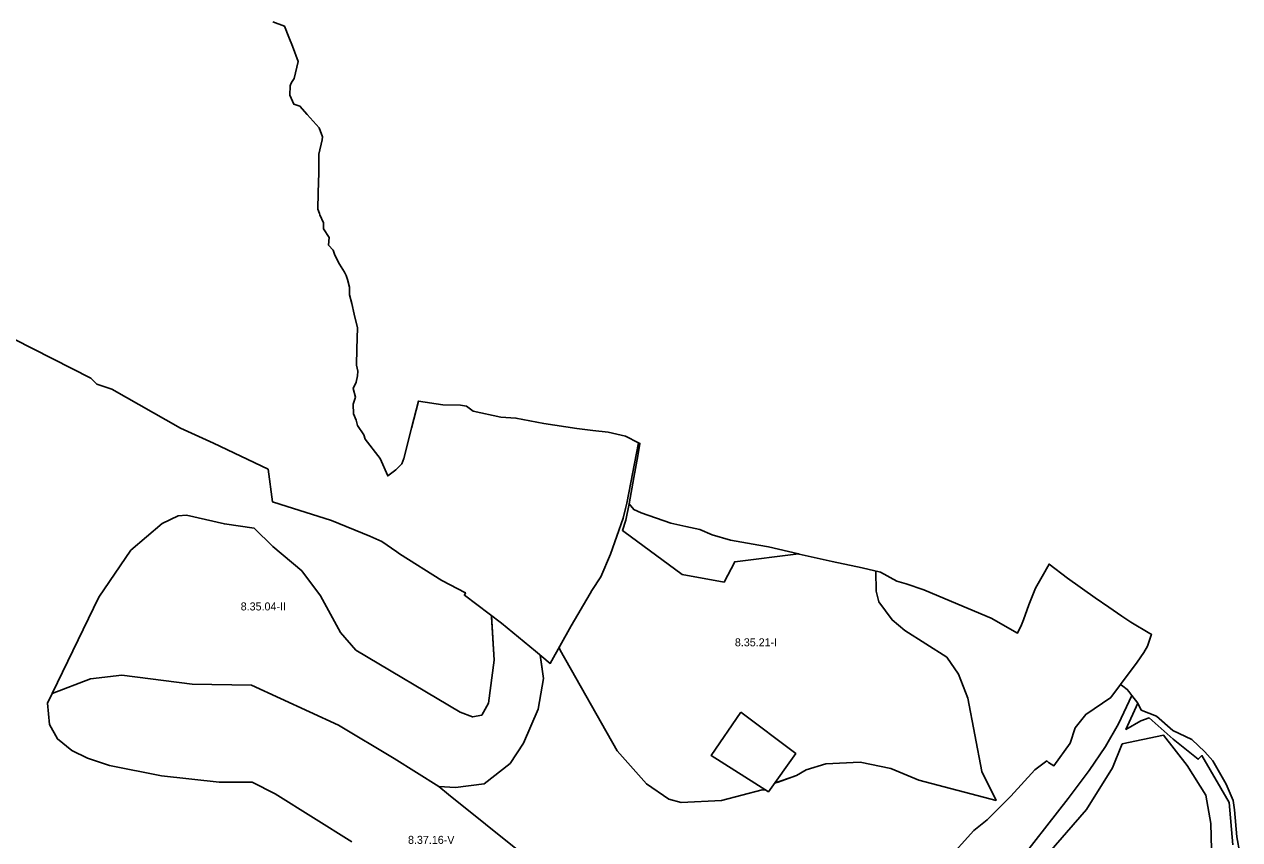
# Model space of a CAD drawing. Extents: x -547623 to -533936, y -1096714 to -1086523.
# Drawn here: x -542784 to -541266, y -1091207 to -1090189 of the extents above; entities that cross this region are included whole.
import ezdxf

# ---------------------------------------------------------------- set-up
doc = ezdxf.new("R2010")
doc.units = 0
for name, color, linetype in [('Vrstva 27', 7, 'Continuous'), ('Vrstva 28', 7, 'Continuous'), ('Vrstva 29', 7, 'Continuous')]:
    doc.layers.add(name, color=color, linetype=linetype)

msp = doc.modelspace()

# ---------------------------------------------------------------- linework, layer by layer
at = {"layer": 'Vrstva 28'}
for p, q in [((-542612, -1090812.5), (-542592, -1090803)), ((-542592, -1090803), (-542612, -1090812.5)), ((-542592, -1090803), (-542581.5, -1090802)), ((-542581.5, -1090802), (-542592, -1090803)), ((-542581.5, -1090802), (-542534, -1090813)), ((-542534, -1090813), (-542581.5, -1090802)), ((-542651, -1090846), (-542612, -1090812.5)), ((-542612, -1090812.5), (-542651, -1090846)), ((-542534, -1090813), (-542497, -1090818.5)), ((-542497, -1090818.5), (-542534, -1090813)), ((-542497, -1090818.5), (-542473.5, -1090841.5)), ((-542473.5, -1090841.5), (-542497, -1090818.5)), ((-542691, -1090904.5), (-542651, -1090846)), ((-542651, -1090846), (-542691, -1090904.5)), ((-542473.5, -1090841.5), (-542437.5, -1090871.5)), ((-542437.5, -1090871.5), (-542473.5, -1090841.5)), ((-541780.9, -1090858.6), (-541780.9, -1090858.6)), ((-542437.5, -1090871.5), (-542414, -1090903)), ((-542414, -1090903), (-542437.5, -1090871.5)), ((-541720.5, -1090871.9), (-541720.5, -1090871.9)), ((-542749, -1091025), (-542691, -1090904.5)), ((-542691, -1090904.5), (-542749, -1091025)), ((-542414, -1090903), (-542389, -1090948.5)), ((-542389, -1090948.5), (-542414, -1090903)), ((-542200.6, -1090927.6), (-542197, -1090983)), ((-542197, -1090983), (-542200.5, -1090929)), ((-542389, -1090948.5), (-542370, -1090970.5)), ((-542370, -1090970.5), (-542389, -1090948.5)), ((-542370, -1090970.5), (-542239.5, -1091048)), ((-542239.5, -1091048), (-542370, -1090970.5)), ((-542204, -1091037), (-542197, -1090983)), ((-542197, -1090983), (-542204, -1091037)), ((-542662, -1091002), (-542701.5, -1091006.5)), ((-542701.5, -1091006.5), (-542662, -1091002)), ((-542574.5, -1091013), (-542662, -1091002)), ((-542662, -1091002), (-542574.5, -1091013)), ((-542701.5, -1091006.5), (-542749, -1091025)), ((-542749, -1091025), (-542701.5, -1091006.5)), ((-542500, -1091014.5), (-542574.5, -1091013)), ((-542574.5, -1091013), (-542500, -1091014.5)), ((-542391.5, -1091064.5), (-542500, -1091014.5)), ((-542500, -1091014.5), (-542391.5, -1091064.5)), ((-542135.5, -1091006), (-542142, -1091044.5)), ((-542749, -1091025), (-542755, -1091037)), ((-542755, -1091037), (-542749, -1091025)), ((-542755, -1091037), (-542752.5, -1091063.5)), ((-542752.5, -1091063.5), (-542755, -1091037)), ((-542239.5, -1091048), (-542224, -1091054)), ((-542224, -1091054), (-542239.5, -1091048)), ((-542212.5, -1091052), (-542204, -1091037)), ((-542204, -1091037), (-542212.5, -1091052)), ((-542142, -1091044.5), (-542160.5, -1091087)), ((-542224, -1091054), (-542212.5, -1091052)), ((-542212.5, -1091052), (-542224, -1091054)), ((-542752.5, -1091063.5), (-542742.5, -1091081.5)), ((-542742.5, -1091081.5), (-542752.5, -1091063.5)), ((-542322, -1091106), (-542391.5, -1091064.5)), ((-542391.5, -1091064.5), (-542322, -1091106)), ((-542742.5, -1091081.5), (-542724.5, -1091096)), ((-542724.5, -1091096), (-542742.5, -1091081.5)), ((-542160.5, -1091087), (-542177, -1091112)), ((-542724.5, -1091096), (-542705, -1091105.5)), ((-542705, -1091105.5), (-542724.5, -1091096)), ((-542705, -1091105.5), (-542677.5, -1091114.5)), ((-542677.5, -1091114.5), (-542705, -1091105.5)), ((-542266, -1091141), (-542322, -1091106)), ((-542322, -1091106), (-542266, -1091141)), ((-542677.5, -1091114.5), (-542612.5, -1091127.5)), ((-542612.5, -1091127.5), (-542677.5, -1091114.5)), ((-542177, -1091112), (-542209.5, -1091137.5)), ((-542612.5, -1091127.5), (-542540.5, -1091135.5)), ((-542540.5, -1091135.5), (-542612.5, -1091127.5)), ((-542540.5, -1091135.5), (-542499.5, -1091135.5)), ((-542499.5, -1091135.5), (-542540.5, -1091135.5)), ((-542499.5, -1091135.5), (-542470.5, -1091150)), ((-542470.5, -1091150), (-542499.5, -1091135.5)), ((-542209.5, -1091137.5), (-542245.5, -1091142)), ((-542470.5, -1091150), (-542375, -1091210)), ((-542375, -1091210), (-542470.5, -1091150)), ((-542245.5, -1091142), (-542266, -1091141)), ((-542266, -1091141), (-542254, -1091151)), ((-542254, -1091151), (-542161.5, -1091225))]:
    msp.add_line(p, q, dxfattribs=at)
for points in [[(-542796.8, -1090582.4), (-542700.9, -1090631.2), (-542693.2, -1090638.7), (-542674.6, -1090645), (-542588.8, -1090693.4), (-542547.8, -1090712.1), (-542479.5, -1090744.8), (-542473.9, -1090785.7), (-542464.9, -1090788.5), (-542400.3, -1090808.8), (-542352.2, -1090828.5), (-542337.4, -1090835), (-542318.8, -1090848), (-542315.2, -1090850.3), (-542262.4, -1090883.7), (-542232.9, -1090899.1), (-542234.2, -1090902.1), (-542187.9, -1090937.2), (-542145.5, -1090972), (-542127.1, -1090987.2), (-542100.8, -1090940.4), (-542077.2, -1090899.8), (-542075.2, -1090896.3), (-542063.8, -1090879.2), (-542051.9, -1090850.9), (-542035.8, -1090806), (-542033, -1090793.8), (-542031.5, -1090787), (-542017, -1090711.7), (-542033.2, -1090703.4), (-542054.6, -1090698.6), (-542073.8, -1090696.3), (-542093.9, -1090693.9), (-542135, -1090687.7), (-542170, -1090680.9), (-542188.7, -1090679.9), (-542223.5, -1090672.4), (-542231.8, -1090666.1), (-542239, -1090664.9), (-542261.2, -1090664.6), (-542291.7, -1090659.8), (-542300.3, -1090693.7), (-542310.1, -1090731.5), (-542312.5, -1090738.1), (-542320, -1090745.4), (-542330, -1090753.1), (-542339.5, -1090731.6), (-542358.4, -1090707.5), (-542359.9, -1090702.1), (-542368, -1090690.2), (-542369.6, -1090683.6), (-542372.8, -1090675.5), (-542373.2, -1090663.6), (-542370.5, -1090655), (-542373.2, -1090644.1), (-542369.3, -1090636), (-542368, -1090628.1), (-542367.4, -1090622.4), (-542369.1, -1090614.8), (-542368.5, -1090594.5), (-542367.8, -1090568.4), (-542371.8, -1090551.4), (-542375, -1090538.1), (-542377.6, -1090527), (-542377.6, -1090517.7), (-542380.4, -1090507.8), (-542381.9, -1090503), (-542384.1, -1090499), (-542390.1, -1090488.8), (-542396, -1090477.8), (-542398.2, -1090471.5), (-542403.9, -1090465.1), (-542403.2, -1090455.5), (-542410.1, -1090444.7), (-542410.1, -1090437.1), (-542414.7, -1090427.3), (-542415.4, -1090425.6), (-542417.2, -1090420.1), (-542416.9, -1090399.8), (-542416.3, -1090374.6), (-542416.1, -1090351.7), (-542411.8, -1090333.5), (-542411.6, -1090329.8), (-542415.8, -1090318.7), (-542430.8, -1090301.9), (-542439.8, -1090291.6), (-542447.3, -1090289.2), (-542452.2, -1090277.8), (-542452, -1090266.3), (-542451.1, -1090263.9), (-542449.4, -1090261), (-542446.9, -1090257), (-542442.1, -1090235.8), (-542449.2, -1090216.6), (-542453.4, -1090205.5), (-542458.8, -1090191.6), (-542473.6, -1090186.5)], [(-541265.8, -1091224.5), (-541269.6, -1091203.8), (-541272.5, -1091169.9), (-541273.9, -1091158.3), (-541282.7, -1091138), (-541299.3, -1091108.7), (-541309.3, -1091097.6), (-541325.8, -1091082.1), (-541349.2, -1091070.9), (-541369.6, -1091053.2), (-541388.8, -1091045.5), (-541393.2, -1091036.7), (-541400.5, -1091027.1), (-541404.2, -1091022.4), (-541406.2, -1091019.8), (-541411.8, -1091015.7), (-541414.9, -1091013.4), (-541393.8, -1090985.6), (-541385.4, -1090973.5), (-541380.8, -1090965.8), (-541376.2, -1090950.9), (-541378.2, -1090949.7), (-541401.9, -1090935.6), (-541413.2, -1090928.4), (-541429.2, -1090917), (-541446.3, -1090905.3), (-541480.9, -1090880.7), (-541504, -1090863.2), (-541512.7, -1090878.9), (-541521.1, -1090893.2), (-541529.2, -1090914.2), (-541535.8, -1090932.7), (-541538.2, -1090939.1), (-541543.5, -1090949.6), (-541576.4, -1090930.9), (-541633.8, -1090906.6), (-541660.2, -1090895.4), (-541682.5, -1090888.1), (-541694.1, -1090884.6), (-541714.3, -1090873.4), (-541737.4, -1090868), (-541774.7, -1090860), (-541816, -1090850.8), (-541817, -1090850.6), (-541854.4, -1090841.9), (-541866.3, -1090839.7), (-541901.8, -1090833.5), (-541924.7, -1090826.6), (-541940.3, -1090819.9), (-541957.5, -1090816.4), (-541976.2, -1090812.2), (-542013.6, -1090799.4), (-542022.7, -1090794.9), (-542028.3, -1090788.2), (-542022.6, -1090755.3), (-542017.6, -1090728.1), (-542015, -1090712.7), (-542017, -1090711.7), (-542033.2, -1090703.4), (-542054.6, -1090698.6), (-542073.8, -1090696.3), (-542093.9, -1090693.9), (-542135, -1090687.7), (-542170, -1090680.9), (-542188.7, -1090679.9), (-542223.5, -1090672.4), (-542231.8, -1090666.1), (-542239, -1090664.9), (-542261.2, -1090664.6), (-542291.7, -1090659.8), (-542300.3, -1090693.7), (-542310.1, -1090731.5), (-542312.5, -1090738.1), (-542320, -1090745.4), (-542330, -1090753.1), (-542339.5, -1090731.6), (-542358.4, -1090707.5), (-542359.9, -1090702.1), (-542368, -1090690.2), (-542369.6, -1090683.6), (-542372.8, -1090675.5), (-542373.2, -1090663.6), (-542370.5, -1090655), (-542373.2, -1090644.1), (-542369.3, -1090636), (-542368, -1090628.1), (-542367.4, -1090622.4), (-542369.1, -1090614.8), (-542368.5, -1090594.5), (-542367.8, -1090568.4), (-542371.8, -1090551.4), (-542375, -1090538.1), (-542377.6, -1090527), (-542377.6, -1090517.7), (-542380.4, -1090507.8), (-542381.9, -1090503), (-542384.1, -1090499), (-542390.1, -1090488.8), (-542396, -1090477.8), (-542398.2, -1090471.5), (-542403.9, -1090465.1), (-542403.2, -1090455.5), (-542410.1, -1090444.7), (-542410.1, -1090437.1), (-542414.7, -1090427.3), (-542415.4, -1090425.6), (-542417.2, -1090420.1), (-542416.9, -1090399.8), (-542416.3, -1090374.6), (-542416.1, -1090351.7), (-542411.8, -1090333.5), (-542411.6, -1090329.8), (-542415.8, -1090318.7), (-542430.8, -1090301.9), (-542439.8, -1090291.6), (-542447.3, -1090289.2), (-542452.2, -1090277.8), (-542452, -1090266.3), (-542451.1, -1090263.9), (-542449.4, -1090261), (-542446.9, -1090257), (-542442.1, -1090235.8), (-542449.2, -1090216.6), (-542453.4, -1090205.5), (-542458.8, -1090191.6), (-542473.6, -1090186.5)], [(-541909.8, -1090886), (-541896.6, -1090860.3), (-541817, -1090850.6), (-541854.4, -1090841.9), (-541866.3, -1090839.7), (-541901.8, -1090833.5), (-541924.7, -1090826.6), (-541940.3, -1090819.9), (-541957.5, -1090816.4), (-541976.2, -1090812.2), (-542013.6, -1090799.4), (-542022.7, -1090794.9), (-542028.3, -1090788.2), (-542032.7, -1090808.6), (-542036.9, -1090821.2), (-542035.1, -1090822.6), (-541962.2, -1090876.3), (-541909.8, -1090886)], [(-542239.5, -1091048), (-542370, -1090970.5), (-542389, -1090948.5), (-542414, -1090903), (-542437.5, -1090871.5), (-542473.5, -1090841.5), (-542497, -1090818.5), (-542534, -1090813), (-542581.5, -1090802), (-542592, -1090803), (-542612, -1090812.5), (-542651, -1090846), (-542691, -1090904.5), (-542749, -1091025), (-542701.5, -1091006.5), (-542662, -1091002), (-542574.5, -1091013), (-542500, -1091014.5), (-542391.5, -1091064.5), (-542322, -1091106), (-542266, -1091141), (-542245.5, -1091142), (-542209.5, -1091137.5), (-542177, -1091112), (-542160.5, -1091087), (-542142, -1091044.5), (-542135.5, -1091006), (-542139.7, -1090976.9)], [(-541780.9, -1090858.6), (-541780.9, -1090858.6)], [(-541720.5, -1090871.9), (-541720, -1090897), (-541716.5, -1090910.5), (-541700, -1090933), (-541684, -1090946), (-541631.5, -1090979.5), (-541617, -1091000.5), (-541605.5, -1091030.5), (-541588, -1091122), (-541570.1, -1091158.2), (-541666.5, -1091133), (-541701.5, -1091118.5), (-541740, -1091110.5), (-541783, -1091112.5), (-541807.5, -1091120), (-541819.5, -1091127), (-541846.9, -1091136.9)], [(-541843.7, -1091135.7), (-541819.5, -1091127), (-541807.5, -1091120), (-541783, -1091112.5), (-541740, -1091110.5), (-541701.5, -1091118.5), (-541666.5, -1091133), (-541570.1, -1091158.2), (-541588, -1091122), (-541605.5, -1091030.5), (-541617, -1091000.5), (-541631.5, -1090979.5), (-541684, -1090946), (-541700, -1090933), (-541716.5, -1090910.5), (-541720, -1090897), (-541720.5, -1090871.9)], [(-542200.5, -1090929), (-542197, -1090983), (-542204, -1091037), (-542212.5, -1091052), (-542224, -1091054), (-542239.5, -1091048)], [(-542116.1, -1090967.5), (-542114.5, -1090970.5), (-542043.5, -1091096.5), (-542007, -1091137.5), (-541979, -1091156.5), (-541963.5, -1091161), (-541913, -1091158.5), (-541862.5, -1091145), (-541858, -1091145.3)], [(-542176.8, -1091480.2), (-542147, -1091427), (-542133.5, -1091384.5), (-542112, -1091362), (-542125, -1091305), (-542132, -1091278.5), (-542142.5, -1091252), (-542161.5, -1091225), (-542254, -1091151), (-542266, -1091141), (-542245.5, -1091142), (-542209.5, -1091137.5), (-542177, -1091112), (-542160.5, -1091087), (-542142, -1091044.5), (-542135.5, -1091006), (-542138.9, -1090982.2)], [(-542161.5, -1091225), (-542254, -1091151), (-542266, -1091141), (-542322, -1091106), (-542391.5, -1091064.5), (-542500, -1091014.5), (-542574.5, -1091013), (-542662, -1091002), (-542701.5, -1091006.5), (-542749, -1091025), (-542755, -1091037), (-542752.5, -1091063.5), (-542742.5, -1091081.5), (-542724.5, -1091096), (-542705, -1091105.5), (-542677.5, -1091114.5), (-542612.5, -1091127.5), (-542540.5, -1091135.5), (-542499.5, -1091135.5), (-542470.5, -1091150), (-542375, -1091210)], [(-541506.8, -1091190.1), (-541480, -1091155.8), (-541453.8, -1091121), (-541433.4, -1091090.9), (-541417.3, -1091062.7), (-541400.5, -1091027.1), (-541404.2, -1091022.4), (-541406.2, -1091019.8), (-541411.8, -1091015.7), (-541414.9, -1091013.4), (-541426.6, -1091029.6), (-541458.2, -1091050.9), (-541471.2, -1091067.6), (-541477.4, -1091086.9), (-541497.9, -1091114.9), (-541504.5, -1091111.1), (-541506.7, -1091109), (-541521.6, -1091120.1), (-541551.8, -1091152.8), (-541554.7, -1091155.9), (-541581.2, -1091182.4), (-541591.5, -1091190.9), (-541598, -1091195.7), (-541632.3, -1091233.9)], [(-541393.2, -1091036.7), (-541408, -1091069.7), (-541389.3, -1091058.8), (-541378.8, -1091055.2), (-541348.9, -1091081.9), (-541317.7, -1091106.8), (-541313.1, -1091102.3), (-541279.1, -1091161), (-541274.4, -1091213.9)], [(-541265.8, -1091224.5), (-541269.6, -1091203.8), (-541272.5, -1091169.9), (-541273.9, -1091158.3), (-541282.7, -1091138), (-541299.3, -1091108.7), (-541309.3, -1091097.6), (-541325.8, -1091082.1), (-541349.2, -1091070.9), (-541369.6, -1091053.2), (-541388.8, -1091045.5), (-541393.2, -1091036.7)], [(-541888.8, -1091048.3), (-541926.1, -1091102), (-541854.5, -1091147.5), (-541820.4, -1091099.7), (-541888.8, -1091048.3)], [(-541539.3, -1091231.4), (-541506.8, -1091190.1)]]:
    msp.add_lwpolyline(points, dxfattribs=at)
at = {"layer": 'Vrstva 29'}
msp.add_lwpolyline([(-541300.8, -1091235.9), (-541301.9, -1091186.9), (-541308, -1091151.9), (-541331.6, -1091114.7), (-541361, -1091077), (-541412.6, -1091087.7), (-541424.8, -1091117.6), (-541457.1, -1091169.7), (-541559.8, -1091287.3)], dxfattribs=at)

# ---------------------------------------------------------------- texts
at = {"layer": 'Vrstva 27'}
for s, p in [('8.35.04-II', (-542513.7, -1090921.1)), ('8.35.21-I', (-541896.4, -1090965.9)), ('8.37.16-V', (-542304.7, -1091212.5))]:
    msp.add_text(s, height=10, dxfattribs=at).set_placement(p)

doc.saveas('drawing.dxf')
